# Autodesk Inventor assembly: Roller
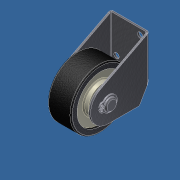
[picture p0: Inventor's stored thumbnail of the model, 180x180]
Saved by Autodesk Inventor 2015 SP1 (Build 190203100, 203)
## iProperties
Category: Mechanical Engineering Drawing and Design - CADD
Manager: Fábio Ricardo de Oliveira Souza
Company: SENAI - Serviço Nacional de Aprendizagem Industrial
Created: 2011-06
Part Number: Roller
Document SubType Name: Assembly
Designer: Guilherme Augusto Franco de Souza
Engineer: George Geraldo de Oliveia Silva
Authority: Fábio Ricardo de Oliveira Soza
Mass: 360.085 g
Surface Area: 273.296 cm^2
Volume: 45.8689 cm^3
Density: 7.8503 g/cm^3
Description: Purchased
Subject: WorldSkill 2011 - London, England
Author: Guilherme Augusto Franco de Souza
Revision Number: 00
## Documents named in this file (7)
- E:\Visitor Experience Project\WSI2015 - Visitor Experience Project\#46- Sheet Metal Technology\01- 3D Models\Outodoor Heater\2- Assemblies\Roller.iam
- E:\Visitor Experience Project\WSI2015 - Visitor Experience Project\#46- Sheet Metal Technology\01- 3D Models\Outodoor Heater\1- Parts\Roller - Support.ipt
- E:\Visitor Experience Project\WSI2015 - Visitor Experience Project\#46- Sheet Metal Technology\01- 3D Models\Outodoor Heater\1- Parts\Roller - Wheel.ipt
- C:\Users\SENAI\Desktop\WorldSkill 2011\Content Center\en-US\DIN BEARING(1)\DIN 625 SKF - SKF 61800.ipt
- E:\Visitor Experience Project\WSI2015 - Visitor Experience Project\#46- Sheet Metal Technology\01- 3D Models\Outodoor Heater\1- Parts\Roller - Spacer.ipt
- E:\Visitor Experience Project\WSI2015 - Visitor Experience Project\#46- Sheet Metal Technology\01- 3D Models\Outodoor Heater\2- Assemblies\Roller\Design Accelerator\Shaft1.iam
- C:\Users\SENAI\Desktop\WorldSkill 2011\Content Center\en-US\DIN 471(1)\DIN 471 - 10x1.ipt
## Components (8 placed, 6 different names)
1. Roller - Support:1 — Insert:5, Insert:6
2. Roller - Wheel:1 — Insert:1, Insert:2
3. DIN 625 SKF 61800:1 — Insert:2, Insert:4
4. DIN 625 SKF 61800:2 — Insert:1, Insert:3
5. Roller - Spacer:1 — Insert:3, Insert:5
6. Roller - Spacer:2 — Insert:4
7. Pin:1 [sub-assembly] — Insert:6, Insert:7
8. DIN 471 10x1:1 — Insert:7
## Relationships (7: Insert 7)
- Insert:1: Roller - Wheel:1 ↔ DIN 625 SKF 61800:2
- Insert:2: Roller - Wheel:1 ↔ DIN 625 SKF 61800:1
- Insert:3: DIN 625 SKF 61800:2 ↔ Roller - Spacer:1
- Insert:4: DIN 625 SKF 61800:1 ↔ Roller - Spacer:2
- Insert:5: Roller - Support:1 ↔ Roller - Spacer:1
- Insert:6: Roller - Support:1 ↔ Pin:1
- Insert:7: Pin:1 ↔ DIN 471 10x1:1
